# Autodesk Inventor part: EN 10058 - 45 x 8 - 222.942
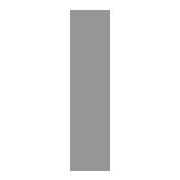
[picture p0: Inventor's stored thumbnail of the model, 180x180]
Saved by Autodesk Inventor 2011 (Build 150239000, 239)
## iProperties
_CCFamilyMember: 49
_CCFamilyDisplayName: DIN EN 10058 - Hot rolled flat steel bars for general purposes
_FrameMemberDoc: Frame Member File
_Version: 15.0.0
_GetPNFromCC: 1
Created: 2010-02
Part Number: EN 10058 - 45 x 8 - 222.942
Material: Steel, Mild
Description: flat steel bar 45*8
Document SubType Name: Modeling
Standard: DIN
Designer: PC
Standard Revision: 2004
Standards Organization: DIN
Language: en-US
Size Designation: 45 x 8
Categories: <MemberInstance><Categories><Category DisplayName="Structural Shapes" InternalName="089c4875-fa83-4c05-b084-43b9cc11f5ed" Mnemonic="GRDR"><CategoryParameter Dis
Stock Number: 45 x 8
Density: 7.86 g/cm^3
IsCustomPart: 1
G_L: 222.942 mm
G_W: 8.000 mm
G_H: 45.000 mm
+1BC0D983-4DBD-44C7-9296-272D917AF5B2+CUTDETAIL1: Cut
Author: PC
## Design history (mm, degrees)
node "Start plane"
node "End plane"
sketch "Sketch"
  geometry: L1 (4, -22.5)-(-4, -22.5); L2 (-4, -22.5)-(-4, 22.5); L3 (-4, 22.5)-(4, 22.5); L4 (4, 22.5)-(4, -22.5); L5 (-6, 0)-(8, 0); L6 (0, -30)-(0, 40); L7 (0, 54)-(0, -44) reference; L8 (-9.2, 0)-(13.2, 0) reference
  constraints: 12 end point, 2 collinear, 2 parallel, 1 horizontal, 1 perpendicular
  dimensions: "d0" = 45 distance between parallel lines of L3 L1 (= G_W); "d1" = 8 distance between parallel lines of L4 L2 (= G_H); "d4" = 4 distance between parallel lines of L6 L4 (= 0.5 x d1); "d5" = 22.5 distance between parallel lines of L5 L3 (= 0.5 x d0)
extrude "Body" new body sketch "Sketch" stored distance "d2" = 222.94229 (= G_L); taper "d3" = 0 deg
node "Driven Length"
  sketch "Sketch3"
    geometry: L1 (0, 0)-(10, 0) reference
    constraints: 2 end point, 1 horizontal
  workplane "Work Plane3"
  sketch "Sketch4"
    geometry: L1 (-2, 0)-(12, 0) reference; L2 (-2, 222.942)-(12, 222.942) reference
    dimensions: "d9" = 222.94229 distance between parallel lines of L1 L2 (derived)
workplane "Work Plane4"
split "Split1"
body "Solid1"
other parameters: "G_W" = 45 [user parameter; used in 1 equation term], "G_H" = 8 [user parameter; used in 1 equation term], "G_L" = 222.94229 (= d9) [user parameter; used in 1 equation term], "G_OFFSET_START" = 0 [user parameter; used in 1 equation term], "G_OFFSET_END" = 77.94229 [user parameter; used in 1 equation term], "d6" = 0 (computed from G_OFFSET_START), "d7" = 222.94229 (= G_OFFSET_END + B_L), "B_L" = 145 [user parameter; used in 1 equation term], "d8" = 90 deg, "MAS" = 0.283 [user parameter]
